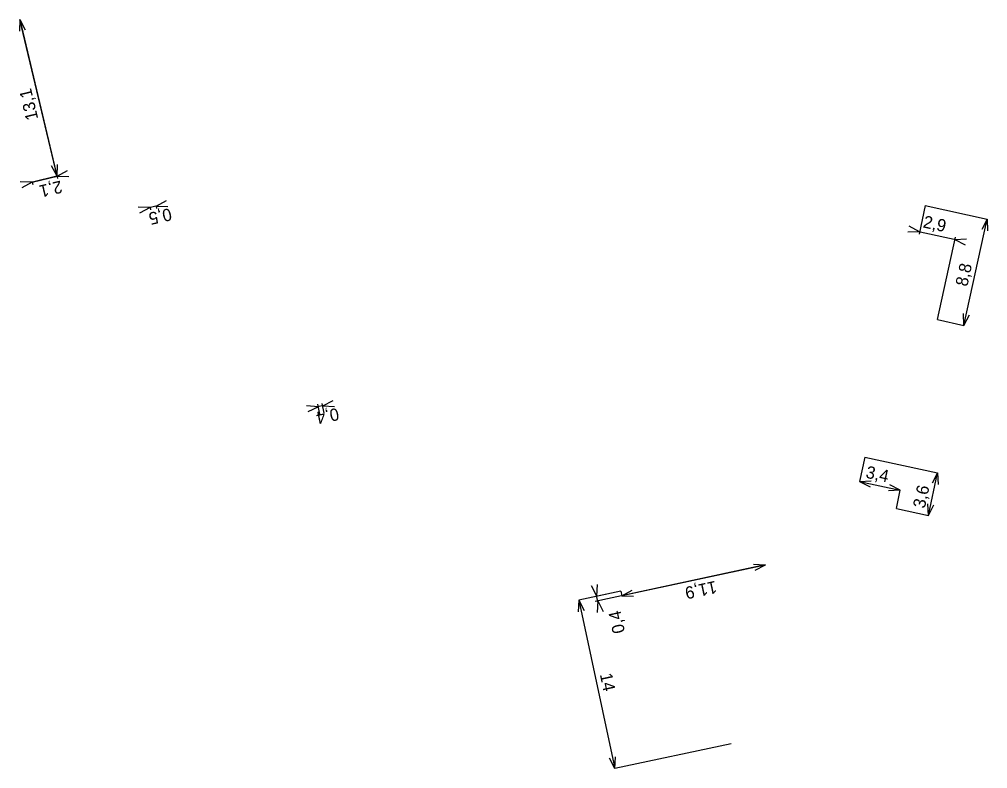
# Model space of a CAD drawing. Extents: x -745245.7 to -745166.8, y -1052486.8 to -1052425.8.
import ezdxf

# ---------------------------------------------------------------- set-up
doc = ezdxf.new("R2010")
doc.units = 0
doc.layers.add('Kota_NN', color=7, linetype='Continuous')
doc.layers.add('Kota_VN', color=7, linetype='Continuous')

msp = doc.modelspace()

# ---------------------------------------------------------------- linework, layer by layer
at = {"layer": 'Kota_NN'}
for p, q in [((-745171.9, -1052440.94), (-745172.405, -1052443.259)), ((-745171.9, -1052440.94), (-745166.864, -1052442.038)), ((-745172.362, -1052443.063), (-745173.216, -1052442.622)), ((-745168.748, -1052450.681), (-745166.864, -1052442.038)), ((-745166.864, -1052442.038), (-745167.305, -1052442.892)), ((-745166.864, -1052442.038), (-745166.819, -1052442.998)), ((-745172.362, -1052443.063), (-745173.322, -1052443.108)), ((-745172.558, -1052443.021), (-745169.294, -1052443.731)), ((-745170.91, -1052450.21), (-745169.447, -1052443.493)), ((-745169.49, -1052443.689), (-745168.53, -1052443.644)), ((-745169.49, -1052443.689), (-745168.636, -1052444.13)), ((-745168.748, -1052450.681), (-745168.793, -1052449.721)), ((-745170.91, -1052450.21), (-745168.748, -1052450.681)), ((-745168.748, -1052450.681), (-745168.307, -1052449.827)), ((-745220.954, -1052457.228), (-745220.095, -1052456.798)), ((-745221.308, -1052457.301), (-745222.267, -1052457.244)), ((-745221.308, -1052457.301), (-745222.167, -1052457.731)), ((-745220.758, -1052457.188), (-745221.504, -1052457.341)), ((-745221.183, -1052457.91), (-745221.348, -1052457.105)), ((-745220.83, -1052457.83), (-745220.994, -1052457.032)), ((-745220.954, -1052457.228), (-745219.995, -1052457.285)), ((-745176.82, -1052461.4), (-745177.249, -1052463.386)), ((-745176.82, -1052461.4), (-745170.895, -1052462.681)), ((-745171.646, -1052466.153), (-745170.895, -1052462.681)), ((-745170.895, -1052462.681), (-745171.334, -1052463.535)), ((-745170.895, -1052462.681), (-745170.849, -1052463.64)), ((-745177.249, -1052463.386), (-745176.29, -1052463.34)), ((-745177.249, -1052463.386), (-745173.929, -1052464.104)), ((-745177.249, -1052463.386), (-745176.395, -1052463.825)), ((-745173.929, -1052464.104), (-745174.783, -1052463.665)), ((-745173.929, -1052464.104), (-745174.888, -1052464.15)), ((-745174.25, -1052465.59), (-745173.929, -1052464.104)), ((-745171.646, -1052466.153), (-745171.692, -1052465.194)), ((-745171.646, -1052466.153), (-745171.207, -1052465.299)), ((-745174.25, -1052465.59), (-745171.646, -1052466.153)), ((-745184.93, -1052470.18), (-745198.761, -1052473.144)), ((-745184.928, -1052470.19), (-745196.611, -1052472.682)), ((-745184.928, -1052470.19), (-745185.888, -1052470.14)), ((-745184.928, -1052470.19), (-745185.784, -1052470.626)), ((-745184.93, -1052470.18), (-745184.928, -1052470.19)), ((-745198.646, -1052472.729), (-745198.597, -1052471.769)), ((-745196.69, -1052472.31), (-745200.103, -1052473.041)), ((-745198.646, -1052472.729), (-745199.083, -1052471.874)), ((-745196.69, -1052472.31), (-745198.841, -1052472.771)), ((-745198.524, -1052473.297), (-745198.688, -1052472.533)), ((-745196.69, -1052472.31), (-745196.611, -1052472.682)), ((-745196.611, -1052472.682), (-745195.755, -1052472.246)), ((-745200.103, -1052473.041), (-745200.152, -1052474.001)), ((-745200.103, -1052473.041), (-745197.165, -1052486.756)), ((-745200.103, -1052473.041), (-745199.666, -1052473.896)), ((-745198.566, -1052473.102), (-745198.615, -1052474.062)), ((-745198.566, -1052473.102), (-745198.129, -1052473.957)), ((-745196.611, -1052472.682), (-745195.651, -1052472.732)), ((-745187.71, -1052484.73), (-745197.165, -1052486.756)), ((-745197.165, -1052486.756), (-745197.602, -1052485.901)), ((-745197.165, -1052486.756), (-745197.116, -1052485.796))]:
    msp.add_line(p, q, dxfattribs=at)
at = {"layer": 'Kota_VN'}
for p, q in [((-745245.63, -1052425.78), (-745245.657, -1052426.74)), ((-745245.63, -1052425.78), (-745245.63, -1052425.78)), ((-745242.587, -1052438.546), (-745245.63, -1052425.78)), ((-745245.63, -1052425.78), (-745245.174, -1052426.625)), ((-745245.63, -1052425.78), (-745242.541, -1052438.74)), ((-745242.587, -1052438.546), (-745243.043, -1052437.701)), ((-745242.587, -1052438.546), (-745242.56, -1052437.586)), ((-745242.393, -1052438.499), (-745244.815, -1052439.076)), ((-745244.62, -1052439.03), (-745242.587, -1052438.546)), ((-745242.587, -1052438.546), (-745241.742, -1052438.09)), ((-745242.587, -1052438.546), (-745241.627, -1052438.573)), ((-745244.62, -1052439.03), (-745245.58, -1052439.003)), ((-745244.62, -1052439.03), (-745245.465, -1052439.486)), ((-745244.62, -1052439.03), (-745244.574, -1052439.225)), ((-745235.013, -1052441.092), (-745235.973, -1052441.057)), ((-745234.331, -1052440.935), (-745235.208, -1052441.137)), ((-745235.015, -1052441.082), (-745234.968, -1052441.287)), ((-745234.528, -1052440.97), (-745234.481, -1052441.175)), ((-745234.526, -1052440.98), (-745233.677, -1052440.531)), ((-745234.526, -1052440.98), (-745233.566, -1052441.015)), ((-745235.013, -1052441.092), (-745235.862, -1052441.541))]:
    msp.add_line(p, q, dxfattribs=at)

# ---------------------------------------------------------------- texts
at = {"layer": 'Kota_NN'}
for s, rotation, p in [('2,9', 347.71385, (-745172.137, -1052442.703)), ('8,8', 77.70502, (-745168.48, -1052447.57)), ('0,4', 191.60577, (-745219.75, -1052457.389)), ('3,4', 347.80076, (-745176.801, -1052463.074)), ('3,6', 77.80093, (-745171.941, -1052465.629)), ('11,9', 192.04256, (-745188.988, -1052471.465)), ('0,4', 102.09352, (-745196.341, -1052475.638)), ('14', 282.09189, (-745198.399, -1052479.087))]:
    msp.add_text(s, height=1, rotation=rotation, dxfattribs=at).set_placement(p)
at = {"layer": 'Kota_VN'}
for s, rotation, p in [('13,1', 103.40432, (-745244.115, -1052433.863)), ('2,1', 193.40599, (-745242.301, -1052438.889)), ('0,5', 192.92008, (-745233.387, -1052441.129))]:
    msp.add_text(s, height=1, rotation=rotation, dxfattribs=at).set_placement(p)

doc.saveas('drawing.dxf')
